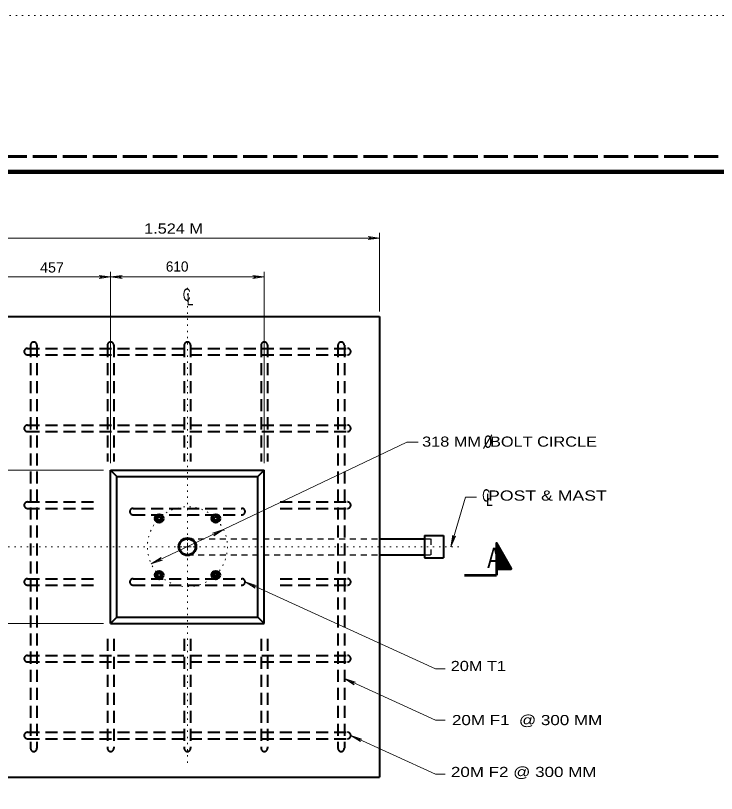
# Model space of a CAD drawing. Extents: x 312583 to 312854, y 144419 to 144597.
# Drawn here: x 312745.2 to 312797.6, y 144538.5 to 144596.8 of the extents above; entities that cross this region are included whole.
import ezdxf
from ezdxf.enums import TextEntityAlignment as Align

# ---------------------------------------------------------------- set-up
doc = ezdxf.new("R2010")
doc.units = 0
doc.header["$LTSCALE"] = 0.3
for name, pattern in [('DOTTED', [1.5, 0.3, -1.2]), ('LONG_DASHED', [7.5, 6, -1.5]), ('MEDIUM_DASHED', [4.5, 3, -1.5]), ('SHORT_DASHED', [2.7, 1.5, -1.2])]:
    doc.linetypes.add(name, pattern=pattern)
for name, color, linetype, lineweight in [('1', 7, 'Continuous', 40), ('2', 7, 'Continuous', 13), ('62', 7, 'DOTTED', 13), ('63', 7, 'LONG_DASHED', 60)]:
    doc.layers.add(name, color=color, linetype=linetype, lineweight=lineweight)

msp = doc.modelspace()

# ---------------------------------------------------------------- linework, layer by layer
at = {"layer": '1'}
for p, q in [((312743.6593, 144574.2486), (312772.4093, 144574.2486)), ((312772.4093, 144574.2486), (312772.4093, 144539.7486)), ((312752.2843, 144551.2486), (312752.2843, 144562.7486)), ((312752.2843, 144562.7486), (312763.7843, 144562.7486)), ((312752.2843, 144562.7486), (312752.7596, 144562.2733)), ((312763.7843, 144562.7486), (312763.3013, 144562.2733)), ((312763.7843, 144551.2486), (312763.7843, 144562.7486)), ((312752.7596, 144551.7316), (312752.7596, 144562.2733)), ((312752.7596, 144562.2733), (312763.3013, 144562.2733)), ((312763.3013, 144551.7316), (312763.3013, 144562.2733)), ((312775.7596, 144557.8419), (312775.7596, 144556.1629)), ((312775.7596, 144557.8419), (312777.201, 144557.8419)), ((312777.201, 144557.8419), (312777.201, 144556.1629)), ((312772.4093, 144557.6043), (312775.7596, 144557.6043)), ((312772.4093, 144556.4006), (312775.7596, 144556.4006)), ((312775.7596, 144556.1629), (312777.201, 144556.1629)), ((312752.2843, 144551.2486), (312752.7596, 144551.7316)), ((312752.2843, 144551.2486), (312763.7843, 144551.2486)), ((312752.7596, 144551.7316), (312763.3013, 144551.7316)), ((312763.3013, 144551.7316), (312763.7843, 144551.2486)), ((312743.6593, 144539.7486), (312772.4093, 144539.7486))]:
    msp.add_line(p, q, dxfattribs=at)
at = {"layer": '1', "linetype": 'MEDIUM_DASHED'}
for p, q in [((312746.0513, 144571.8566), (312770.0096, 144571.8566)), ((312746.2966, 144572.0943), (312746.2966, 144541.9106)), ((312746.772, 144572.0943), (312746.772, 144541.9106)), ((312752.0466, 144572.0943), (312752.0466, 144563.3926)), ((312752.522, 144572.0943), (312752.522, 144563.3926)), ((312757.7966, 144572.0943), (312757.7966, 144563.3926)), ((312758.272, 144572.0943), (312758.272, 144563.3926)), ((312763.5466, 144572.0943), (312763.5466, 144563.3926)), ((312764.022, 144572.0943), (312764.022, 144563.3926)), ((312769.2966, 144572.0943), (312769.2966, 144541.9106)), ((312769.772, 144572.0943), (312769.772, 144541.9106)), ((312746.0513, 144571.3736), (312770.0096, 144571.3736)), ((312746.0513, 144566.1066), (312770.0096, 144566.1066)), ((312746.0513, 144565.6236), (312770.0096, 144565.6236)), ((312746.0513, 144560.3566), (312751.096, 144560.3566)), ((312764.965, 144560.3566), (312770.0096, 144560.3566)), ((312746.0513, 144559.8736), (312751.096, 144559.8736)), ((312753.9633, 144559.8736), (312762.1053, 144559.8736)), ((312753.9633, 144559.3983), (312762.1053, 144559.3983)), ((312764.965, 144559.8736), (312770.0096, 144559.8736)), ((312746.0513, 144554.6066), (312751.096, 144554.6066)), ((312753.9633, 144554.6066), (312762.1053, 144554.6066)), ((312764.965, 144554.6066), (312770.0096, 144554.6066)), ((312746.0513, 144554.1236), (312751.096, 144554.1236)), ((312753.9633, 144554.1236), (312762.1053, 144554.1236)), ((312764.965, 144554.1236), (312770.0096, 144554.1236)), ((312752.0466, 144550.1063), (312752.0466, 144541.9106)), ((312752.522, 144550.1063), (312752.522, 144541.9106)), ((312757.7966, 144550.1063), (312757.7966, 144541.9106)), ((312758.272, 144550.1063), (312758.272, 144541.9106)), ((312763.5466, 144550.1063), (312763.5466, 144541.9106)), ((312764.022, 144550.1063), (312764.022, 144541.9106)), ((312746.0513, 144548.8566), (312770.0096, 144548.8566)), ((312746.0513, 144548.3736), (312770.0096, 144548.3736)), ((312746.0513, 144543.1066), (312770.0096, 144543.1066)), ((312746.0513, 144542.6236), (312770.0096, 144542.6236))]:
    msp.add_line(p, q, dxfattribs=at)
at = {"layer": '1', "linetype": 'SHORT_DASHED', "lineweight": 25}
for p, q in [((312758.0343, 144557.6043), (312772.4093, 144557.6043)), ((312775.7596, 144557.6043), (312776.2426, 144557.6043)), ((312776.2426, 144557.6043), (312776.2426, 144556.4006)), ((312758.0343, 144556.4006), (312772.4093, 144556.4006)), ((312775.7596, 144556.4006), (312776.2426, 144556.4006))]:
    msp.add_line(p, q, dxfattribs=at)
at = {"layer": '1', "lineweight": 158}
msp.add_lwpolyline([(312616.5, 144423.1446), (312616.5, 144585.0846), (312849, 144585.0846)], dxfattribs=at)
at = {"layer": '1', "linetype": 'DOTTED', "lineweight": 13}
msp.add_circle((312758.0324, 144557.002), 2.9948, dxfattribs=at)
at = {"layer": '1', "lineweight": 53}
for centre, radius in [((312755.9149, 144559.1194), 0.2995), ((312760.1498, 144559.1194), 0.2995), ((312755.9149, 144559.1194), 0.1497), ((312760.1498, 144559.1194), 0.1497), ((312755.9149, 144554.8845), 0.2995), ((312755.9149, 144554.8845), 0.1497), ((312760.1498, 144554.8845), 0.2995), ((312760.1498, 144554.8845), 0.1497)]:
    msp.add_circle(centre, radius, dxfattribs=at)
at = {"layer": '1'}
for radius in [0.6589, 0.599]:
    msp.add_circle((312758.0324, 144557.002), radius, dxfattribs=at)
at = {"layer": '1', "linetype": 'MEDIUM_DASHED'}
for centre, start, end in [((312746.5324, 144572.0957), 0, 180), ((312752.2824, 144572.0957), 0, 180), ((312758.0324, 144572.0957), 0, 180), ((312763.7824, 144572.0957), 0, 180), ((312769.5324, 144572.0957), 0, 180), ((312746.0532, 144571.6165), 90, 270), ((312770.0115, 144571.6165), 270, 90), ((312746.0532, 144565.8665), 90, 270), ((312770.0115, 144565.8665), 270, 90), ((312746.0532, 144560.1165), 90, 270), ((312770.0115, 144560.1165), 270, 90), ((312753.9595, 144559.6374), 90, 270), ((312762.1053, 144559.6374), 270, 90), ((312746.0532, 144554.3665), 90, 270), ((312753.9595, 144554.3665), 90, 270), ((312762.1053, 144554.3665), 270, 90), ((312770.0115, 144554.3665), 270, 90), ((312746.0532, 144548.6165), 90, 270), ((312770.0115, 144548.6165), 270, 90), ((312746.0532, 144542.8665), 90, 270), ((312770.0115, 144542.8665), 270, 90), ((312746.5324, 144541.9082), 180, 0), ((312752.2824, 144541.9082), 180, 0), ((312758.0324, 144541.9082), 180, 0), ((312763.7824, 144541.9082), 180, 0), ((312769.5324, 144541.9082), 180, 0)]:
    msp.add_arc(centre, 0.2396, start, end, dxfattribs=at)
at = {"layer": '2'}
for p, q in [((312772.4093, 144574.6243), (312772.4093, 144580.5046)), ((312743.6593, 144580.1213), (312772.4093, 144580.1213)), ((312771.543, 144580.2286), (312771.819, 144580.1213)), ((312772.4093, 144580.1213), (312771.543, 144580.2286)), ((312771.543, 144580.0139), (312771.819, 144580.1213)), ((312772.4093, 144580.1213), (312771.543, 144580.0139)), ((312752.2843, 144563.2699), (312752.2843, 144577.5913)), ((312763.7843, 144563.2699), (312763.7843, 144577.5913)), ((312751.418, 144577.3153), (312751.694, 144577.2079)), ((312752.2843, 144577.2079), (312751.418, 144577.3153)), ((312751.418, 144577.1006), (312751.694, 144577.2079)), ((312752.2843, 144577.2079), (312751.418, 144577.1006)), ((312752.2843, 144577.2079), (312753.1506, 144577.3153)), ((312752.2843, 144577.2079), (312753.1506, 144577.1006)), ((312753.1506, 144577.3153), (312752.8746, 144577.2079)), ((312753.1506, 144577.1006), (312752.8746, 144577.2079)), ((312762.918, 144577.3153), (312763.194, 144577.2079)), ((312763.7843, 144577.2079), (312762.918, 144577.3153)), ((312762.918, 144577.1006), (312763.194, 144577.2079)), ((312763.7843, 144577.2079), (312762.918, 144577.1006)), ((312780.1814, 144564.3597), (312780.8177, 144565.387)), ((312751.74, 144562.7486), (312736.9893, 144562.7486)), ((312760.733, 144558.2866), (312759.905, 144558.0183)), ((312760.733, 144558.2866), (312759.997, 144557.8189)), ((312759.905, 144558.0183), (312760.204, 144558.0336)), ((312759.997, 144557.8189), (312760.204, 144558.0336)), ((312777.7453, 144556.9986), (312777.8833, 144557.8649)), ((312777.7453, 144556.9986), (312778.0903, 144557.8036)), ((312777.8833, 144557.8649), (312777.914, 144557.5659)), ((312778.0903, 144557.8036), (312777.914, 144557.5659)), ((312758.0343, 144556.9986), (312758.0343, 144557.2899)), ((312758.0343, 144556.9986), (312757.743, 144556.9986)), ((312758.0343, 144556.9986), (312758.318, 144556.9986)), ((312758.0343, 144556.9986), (312758.0343, 144556.7149)), ((312755.328, 144555.7183), (312756.064, 144556.1859)), ((312755.328, 144555.7183), (312756.156, 144555.9866)), ((312756.064, 144556.1859), (312755.8646, 144555.9713)), ((312756.156, 144555.9866), (312755.8646, 144555.9713)), ((312762.343, 144554.3689), (312776.5876, 144547.8599)), ((312762.343, 144554.3689), (312763.0866, 144553.9089)), ((312762.343, 144554.3689), (312763.1786, 144554.1006)), ((312763.0866, 144553.9089), (312762.8796, 144554.1236)), ((312763.1786, 144554.1006), (312762.8796, 144554.1236)), ((312751.74, 144551.2486), (312736.9893, 144551.2486)), ((312776.5876, 144547.8599), (312777.316, 144547.8599)), ((312769.772, 144547.1316), (312776.5876, 144544.0189)), ((312769.772, 144547.1316), (312770.5156, 144546.6716)), ((312769.772, 144547.1316), (312770.6076, 144546.8709)), ((312770.5156, 144546.6716), (312770.3086, 144546.8863)), ((312770.6076, 144546.8709), (312770.3086, 144546.8863)), ((312776.5876, 144544.0189), (312777.316, 144544.0189)), ((312770.255, 144542.8689), (312776.5876, 144539.9709)), ((312770.255, 144542.8689), (312770.991, 144542.4089)), ((312770.255, 144542.8689), (312771.083, 144542.6006)), ((312770.991, 144542.4089), (312770.7916, 144542.6236)), ((312771.083, 144542.6006), (312770.7916, 144542.6236)), ((312776.5876, 144539.9709), (312777.316, 144539.9709))]:
    msp.add_line(p, q, dxfattribs=at)
at = {"layer": '2', "linetype": 'DOTTED'}
for p, q in [((312758.0343, 144557.4356), (312758.0343, 144576.6406)), ((312757.605, 144556.9986), (312742.0186, 144556.9986)), ((312758.0343, 144556.5693), (312758.0343, 144540.7223)), ((312758.4636, 144556.9986), (312778.3663, 144556.9986))]:
    msp.add_line(p, q, dxfattribs=at)
at = {"layer": '2', "lineweight": 35}
for p, q in [((312781.1493, 144557.2593), (312781.1646, 144557.2593)), ((312781.1493, 144557.2286), (312781.1723, 144557.2363)), ((312781.1493, 144557.1979), (312781.1876, 144557.2209)), ((312781.1493, 144557.1749), (312781.1953, 144557.1979)), ((312781.1493, 144557.1443), (312781.2106, 144557.1749)), ((312781.1493, 144557.1213), (312781.2183, 144557.1596)), ((312781.1493, 144557.0906), (312781.2336, 144557.1366)), ((312781.1493, 144557.0599), (312781.2413, 144557.1136)), ((312781.1493, 144557.0293), (312781.2566, 144557.0983)), ((312781.1493, 144557.0063), (312781.2643, 144557.0753)), ((312781.1493, 144556.9833), (312781.2796, 144557.0523)), ((312781.1493, 144556.9526), (312781.2873, 144557.0293)), ((312781.1493, 144556.9296), (312781.3026, 144557.0139)), ((312781.1493, 144556.8989), (312781.318, 144556.9909)), ((312781.1493, 144556.8683), (312781.3256, 144556.9679)), ((312781.1493, 144556.8376), (312781.341, 144556.9526)), ((312781.1493, 144556.8146), (312781.3563, 144556.9296)), ((312781.1493, 144556.7839), (312781.364, 144556.9066)), ((312781.1493, 144556.7609), (312781.3793, 144556.8913)), ((312781.1493, 144556.7303), (312781.387, 144556.8683)), ((312781.1493, 144556.6996), (312781.4023, 144556.8453)), ((312781.1493, 144556.6766), (312781.41, 144556.8299)), ((312781.1493, 144556.6459), (312781.4253, 144556.7993)), ((312781.1493, 144556.6229), (312781.433, 144556.7839)), ((312781.1493, 144556.5923), (312781.4483, 144556.7609)), ((312781.1493, 144556.5616), (312781.456, 144556.7379)), ((312781.1493, 144556.5386), (312781.4713, 144556.7226)), ((312781.1493, 144556.5079), (312781.479, 144556.6996)), ((312781.1493, 144556.4849), (312781.4943, 144556.6766)), ((312781.1493, 144556.4543), (312781.5096, 144556.6613)), ((312781.1493, 144556.4313), (312781.5173, 144556.6383)), ((312781.1493, 144556.4006), (312781.5326, 144556.6153)), ((312781.1493, 144556.3699), (312781.548, 144556.5999)), ((312781.1493, 144556.3393), (312781.5556, 144556.5769)), ((312781.1493, 144556.3163), (312781.571, 144556.5539)), ((312781.1493, 144556.2933), (312781.5786, 144556.5309)), ((312781.1493, 144556.2626), (312781.594, 144556.5156)), ((312781.1493, 144556.2319), (312781.6016, 144556.4926)), ((312781.1493, 144556.2089), (312781.617, 144556.4696)), ((312781.1493, 144556.1783), (312781.6246, 144556.4543)), ((312781.1493, 144556.1476), (312781.64, 144556.4313)), ((312781.1493, 144556.1246), (312781.6476, 144556.4083)), ((312781.1493, 144556.0939), (312781.663, 144556.3929)), ((312781.1493, 144556.0633), (312781.6706, 144556.3699)), ((312781.1493, 144556.0403), (312781.686, 144556.3469)), ((312781.1493, 144555.9866), (312781.709, 144556.3009)), ((312781.1493, 144555.9559), (312781.7243, 144556.2856)), ((312781.1493, 144555.9329), (312781.732, 144556.2626)), ((312781.1493, 144555.9023), (312781.7473, 144556.2396)), ((312781.1493, 144555.8716), (312781.755, 144556.2243)), ((312781.1493, 144555.8409), (312781.7703, 144556.2013)), ((312781.1493, 144555.8179), (312781.778, 144556.1783)), ((312781.1493, 144555.7949), (312781.7933, 144556.1629)), ((312781.1493, 144555.7336), (312781.8163, 144556.1169)), ((312781.1493, 144555.7106), (312781.824, 144556.1016)), ((312781.1493, 144555.6799), (312781.8393, 144556.0786)), ((312781.1493, 144555.6493), (312781.8546, 144556.0556)), ((312781.1493, 144555.6263), (312781.8623, 144556.0326)), ((312781.1493, 144555.5956), (312781.8776, 144556.0173)), ((312781.1493, 144555.5649), (312781.893, 144555.9943)), ((312781.1493, 144555.4883), (312781.9236, 144555.9329)), ((312781.1493, 144555.4576), (312781.939, 144555.9099)), ((312781.157, 144556.0096), (312781.7013, 144556.3316)), ((312781.157, 144555.7643), (312781.801, 144556.1399)), ((312781.157, 144555.5419), (312781.9006, 144555.9713)), ((312781.157, 144555.5113), (312781.916, 144555.9559)), ((312781.1493, 144555.4346), (312781.9466, 144555.8946)), ((312781.1493, 144555.4039), (312781.962, 144555.8716)), ((312781.1493, 144555.3733), (312781.9696, 144555.8486)), ((312781.1723, 144555.3579), (312781.985, 144555.8333)), ((312781.226, 144555.3579), (312781.9926, 144555.8026)), ((312781.2643, 144555.3579), (312782.008, 144555.7873)), ((312781.318, 144555.3579), (312782.0156, 144555.7643)), ((312781.364, 144555.3579), (312782.031, 144555.7413)), ((312781.41, 144555.3579), (312782.0463, 144555.7259)), ((312781.456, 144555.3579), (312782.054, 144555.7029)), ((312781.5096, 144555.3579), (312782.0693, 144555.6799)), ((312781.5556, 144555.3579), (312782.0846, 144555.6646)), ((312781.6016, 144555.3579), (312782.0923, 144555.6416)), ((312781.6553, 144555.3579), (312782.1076, 144555.6263)), ((312781.7013, 144555.3579), (312782.1153, 144555.6033)), ((312781.7473, 144555.3579), (312782.1306, 144555.5803)), ((312781.801, 144555.3579), (312782.1383, 144555.5649)), ((312781.847, 144555.3579), (312782.1536, 144555.5343)), ((312781.893, 144555.3579), (312782.1613, 144555.5189)), ((312781.939, 144555.3579), (312782.1766, 144555.4959)), ((312781.9926, 144555.3579), (312782.1843, 144555.4729)), ((312782.031, 144555.3579), (312782.1996, 144555.4576)), ((312782.0846, 144555.3579), (312782.2073, 144555.4346)), ((312782.1306, 144555.3579), (312782.2226, 144555.4116)), ((312782.1843, 144555.3579), (312782.238, 144555.3963)), ((312782.2303, 144555.3579), (312782.2456, 144555.3733))]:
    msp.add_line(p, q, dxfattribs=at)
at = {"layer": '2', "lineweight": 53}
for p in [(312781.1493, 144555.3579), (312778.7573, 144554.8826)]:
    msp.add_line(p, (312781.1493, 144554.8826), dxfattribs=at)
at = {"layer": '2'}
for points in [[(312743.6593, 144577.2079), (312752.2843, 144577.2079), (312763.7843, 144577.2079)], [(312755.328, 144555.7183), (312760.733, 144558.2866), (312774.4563, 144564.8263), (312775.292, 144564.8263)], [(312777.7453, 144556.9986), (312778.8263, 144560.7093), (312779.662, 144560.7093)]]:
    msp.add_lwpolyline(points, dxfattribs=at)
at = {"layer": '2', "lineweight": 53}
msp.add_lwpolyline([(312781.1493, 144555.3579), (312782.261, 144555.3579), (312781.1493, 144557.2746)], close=True, dxfattribs=at)
at = {"layer": '62'}
msp.add_line((312601.2, 144596.7846), (312853.5, 144596.7846), dxfattribs=at)
at = {"layer": '63'}
msp.add_line((312851.75, 144586.2246), (312583.526, 144586.2246), dxfattribs=at)

# ---------------------------------------------------------------- texts
at = {"layer": '2'}
for s, height, width, p in [('1.524 M', 0.76, 1.2, (312754.7877, 144580.4527)), ('457', 0.76, 1.05, (312747.0032, 144577.5393)), ('C', 0.92, 0.65, (312757.6893, 144575.4216)), ('L', 0.92, 0.75, (312757.973, 144575.0843)), ('318 MM  BOLT CIRCLE', 0.76, 1.2, (312775.5921, 144564.4949)), ('C', 0.92, 0.65, (312780.0913, 144560.3873)), ('  POST & MAST', 0.76, 1.3, (312779.7944, 144560.4558)), ('L', 0.92, 0.75, (312780.375, 144560.0499)), ('20M T1', 0.76, 1.2, (312777.7321, 144547.6919)), ('20M F1  @ 300 MM', 0.76, 1.25, (312777.8262, 144543.6416)), ('20M F2 @ 300 MM', 0.76, 1.25, (312777.7475, 144539.7569))]:
    msp.add_text(s, height=height, dxfattribs=dict(at, width=width)).set_placement(p)
msp.add_text('610', height=0.76, dxfattribs=at).set_placement((312756.4134, 144577.6095))
for s, height, width, p in [('0', 0.92, 0.85, (312780.5187, 144564.4134)), ('A', 1.533, 0.75, (312780.9768, 144555.4039))]:
    msp.add_text(s, height=height, dxfattribs=dict(at, width=width)).set_placement(p, align=Align.CENTER)

doc.saveas('drawing.dxf')
